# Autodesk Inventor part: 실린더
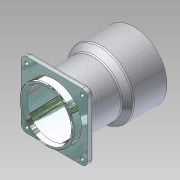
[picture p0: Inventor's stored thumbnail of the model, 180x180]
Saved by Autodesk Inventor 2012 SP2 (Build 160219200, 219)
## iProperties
Manager: KYOUNG IL JANG
Company: 한국ATC센터
Created: 2012-10
Part Number: 실린더
Material: 기본값
Document SubType Name: 모델링
Density: 1 g/cm^3
Checked By: KYOUNG IL JANG
Vendor: CBT Solutions
Designer: KYOUNG IL JANG
Author: KYOUNG IL JANG
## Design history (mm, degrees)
sketch "스케치1"
  geometry: L1 (0, 0)-(0, 112); L2 (30, 0)-(30, 112); L3 (30, 112)-(42.5, 112); L4 (42.5, 112)-(42.5, 69); L5 (42.5, 69)-(35, 61); L6 (35, 61)-(35, 0); L7 (35, 0)-(30, 0)
  constraints: 14 end point, 4 parallel, 2 point on line, 1 perpendicular, 1 vertical
  dimensions: "d0" = 112 distance of L1.start L1.end; "d2" = 85 diameter of L4 L1; "d3" = 70 diameter of L6 L1; "d5" = 60 diameter of L2 L1; "d33" = 43 distance of L3.end L4.end; "d34" = 51 distance from line of L3 L5.end
revolve "회전1" stored, may be unused: angle "d6" = 90 deg
node "작업 평면1"
sketch "스케치2"
  geometry: L1 (-42.5, 42.5)-(42.5, 42.5); L2 (42.5, 42.5)-(42.5, -42.5); L3 (42.5, -42.5)-(-42.5, -42.5); L4 (-42.5, -42.5)-(-42.5, 42.5); C1 r 35 at (0, 0) reference; 3 further points
  constraints: 8 end point, 2 midpoint, 2 parallel, 2 perpendicular, 1 horizontal, 1 horizontal alignment, 1 vertical alignment
  dimensions: "d8" = 85 distance of L1.end L2.end
extrude "돌출1" join sketch "스케치2" distance "d9" = 8; taper "d10" = 0 deg
fillet "모깎기1" dims "d11" = 7, "d12" = 3
sketch "스케치3"
  geometry: L1 (0, 42.5)-(0, 30); 4 further points
  constraints: 2 end point, 2 vertical alignment, 1 midpoint, 1 point on line, 1 vertical, 2 other
hole "구멍1" sketch "스케치3" at (0, 36.25) diameter "d14" = 4.134; stored, may be unused: countersink angle "d18" = 90 deg, drill point angle "d20" = 118 deg; dims "d15" = 12, "d16" = 4, "d17" = 2, "d19" = 15
sketch "스케치4"
  geometry: C1 r 1.621 at (35.5, -35.5) reference; C2 r 1.621 at (35.5, 35.5) reference; C3 r 1.621 at (-35.5, -35.5) reference; C4 r 1.621 at (-35.5, 35.5) reference; 1 further point
hole "구멍2" sketch "스케치4" at (35.5, 35.5), (35.5, -35.5), (-35.5, -35.5), (-35.5, 35.5) diameter "d26" = 4.5; stored, may be unused: countersink angle "d30" = 90 deg, drill point angle "d32" = 118 deg; dims "d27" = 12, "d28" = 8, "d29" = 4.4, "d31" = 15
chamfer "모따기1" distance "d35" = 5; stored, may be unused: second distance "d36" = 2, angle "d37" = 20 deg
chamfer "모따기2" distance "d38" = 1; stored, may be unused: second distance "d39" = 2, angle "d40" = 20 deg
node "솔리드1"
pattern_circular "원형 패턴1" dims angle "d22" = 360 deg
node "참조1"
node "참조2"
node "참조3"
node "참조4"
other parameters: "KFactor" = 4.4
